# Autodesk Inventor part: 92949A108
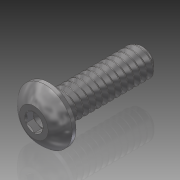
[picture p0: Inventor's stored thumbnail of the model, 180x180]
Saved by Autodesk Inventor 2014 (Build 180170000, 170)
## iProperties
Created: 2013-12
Part Number: 92949A108
Material: Stainless Steel
Document SubType Name: Modeling
Designer: Brad Factor
Density: 8.08 g/cm^3
Appearance: Semi-Polished
Sending System: SolidWorks 2009
Last Author: t5sad
Desc1: 18-8 Stainless Steel Button
Desc2: Socket Head Cap Screw
Desc3: © 2012 McMaster-Carr Supply Company
UNIT_OF_MEASURE: - none -
Author: Brad Factor
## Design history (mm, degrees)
node "92949A1081"
  sketch "3D Sketch1"
node "Cut-Extrude5"
node "Base1"
